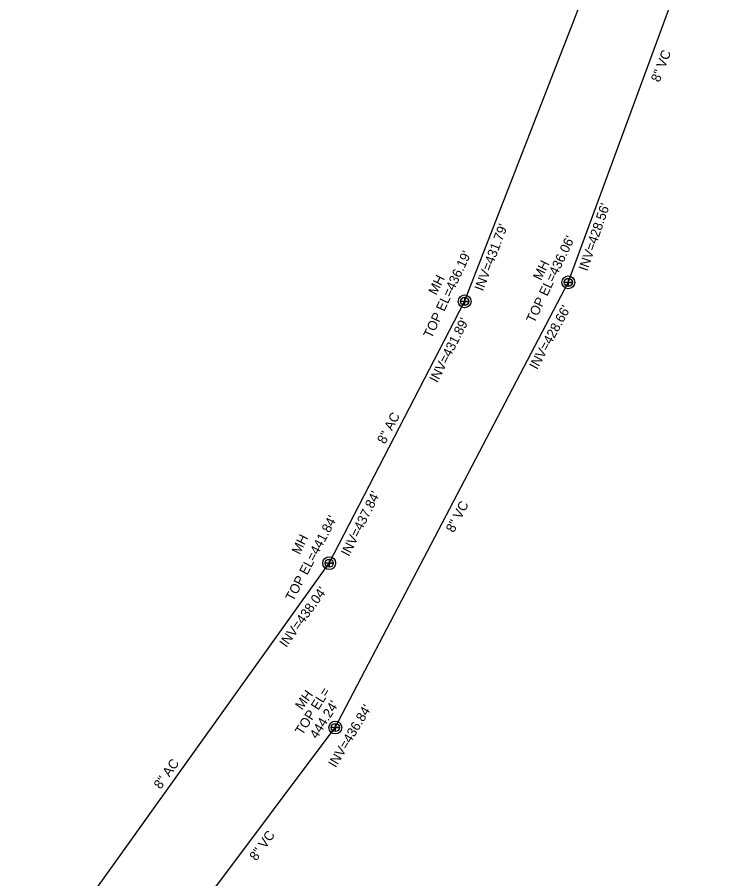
# Model space of a CAD drawing. Extents: x 1975698 to 1978521, y 778259 to 782969.
# Drawn here: x 1977046.9 to 1977349.8, y 780278.8 to 780640.2 of the extents above; entities that cross this region are included whole.
import ezdxf

# ---------------------------------------------------------------- set-up
doc = ezdxf.new("R2010")
doc.units = 0
for name, color, linetype in [('Old_Level_11', 7, 'Continuous'), ('Prop Horizontal Alignment', 7, 'Continuous'), ('Prop Horizontal Alignment Station Label', 7, 'Continuous'), ('Prop WCC CELL', 7, 'Continuous')]:
    doc.layers.add(name, color=color, linetype=linetype)

# ---------------------------------------------------------------- blocks, each defined once
blk = doc.blocks.new('EXIST UTILITIES SANITARY SEWER MANHOLE')
at = {"layer": 'Prop Horizontal Alignment'}
blk.add_lwpolyline([(0, 0.0342), (0, -0.0342), (0, 0), (0.0342, 0), (-0.0342, 0)], dxfattribs=at)
for radius in [0.0539, 0.0342]:
    blk.add_circle((0, 0), radius, dxfattribs=at)

msp = doc.modelspace()

# ---------------------------------------------------------------- linework, layer by layer
at = {"layer": 'Prop Horizontal Alignment Station Label'}
for p, q in [((1977234.68, 780520.98), (1977347.49, 780810.62)), ((1977278.19, 780528.95), (1977349.76, 780723.04)), ((1977180.4, 780342.25), (1977278.19, 780528.95)), ((1977177.86, 780411.19), (1977234.68, 780520.98)), ((1977046.91, 780228.38), (1977177.86, 780411.19)), ((1977106, 780243.3), (1977180.4, 780342.25))]:
    msp.add_line(p, q, dxfattribs=at)

# ---------------------------------------------------------------- block references
at = {"layer": 'Prop Horizontal Alignment', "xscale": 50, "yscale": 50}
for p in [(1977278.19, 780528.95), (1977234.68, 780520.98), (1977177.86, 780411.19), (1977180.4, 780342.25)]:
    msp.add_blockref('EXIST UTILITIES SANITARY SEWER MANHOLE', p, dxfattribs=at)

# ---------------------------------------------------------------- texts
at = {"layer": 'Old_Level_11'}
for s, rotation, p in [('8" VC', 68.719, (1977316.43, 780612.62)), ('8" AC', 62.355, (1977201.28, 780460.88)), ('8" VC', 62.355, (1977230.12, 780423.72)), ('8" AC', 54.385, (1977107.08, 780316.1)), ('8" VC', 54.385, (1977147.26, 780286.02))]:
    msp.add_text(s, height=4, rotation=rotation, dxfattribs=at).set_placement(p)
at = {"layer": 'Prop WCC CELL'}
for s, rotation, p in [("INV=428.56'", 71.0168, (1977286.14, 780533.42)), ("INV=431.79'", 69.0654, (1977242.37, 780525.03)), ("TOP EL=436.06'", 64.433, (1977263.93, 780511.6)), ("TOP EL=436.19'", 64.8765, (1977220.8, 780505.18)), ('MH', 63.4918, (1977266.74, 780529.49)), ('MH', 63.4918, (1977222.81, 780523.3)), ("INV=428.66'", 61.1413, (1977265.07, 780492.1)), ("INV=431.89'", 62.9247, (1977223.23, 780486.57)), ("INV=437.84'", 63.322, (1977186.12, 780413.76)), ("TOP EL=441.84'", 62.1171, (1977162.75, 780394.87)), ('MH', 63.8379, (1977165.47, 780414.52)), ("INV=438.04'", 54.1727, (1977159.83, 780375.57)), ('TOP EL=', 57.6363, (1977166.57, 780338.73)), ('MH', 54.7026, (1977166.48, 780349.32)), ("444.24'", 57.6363, (1977172.7, 780337.2)), ("INV=436.84'", 58.8821, (1977180.58, 780325.13))]:
    msp.add_text(s, height=4, rotation=rotation, dxfattribs=at).set_placement(p)

doc.saveas('drawing.dxf')
